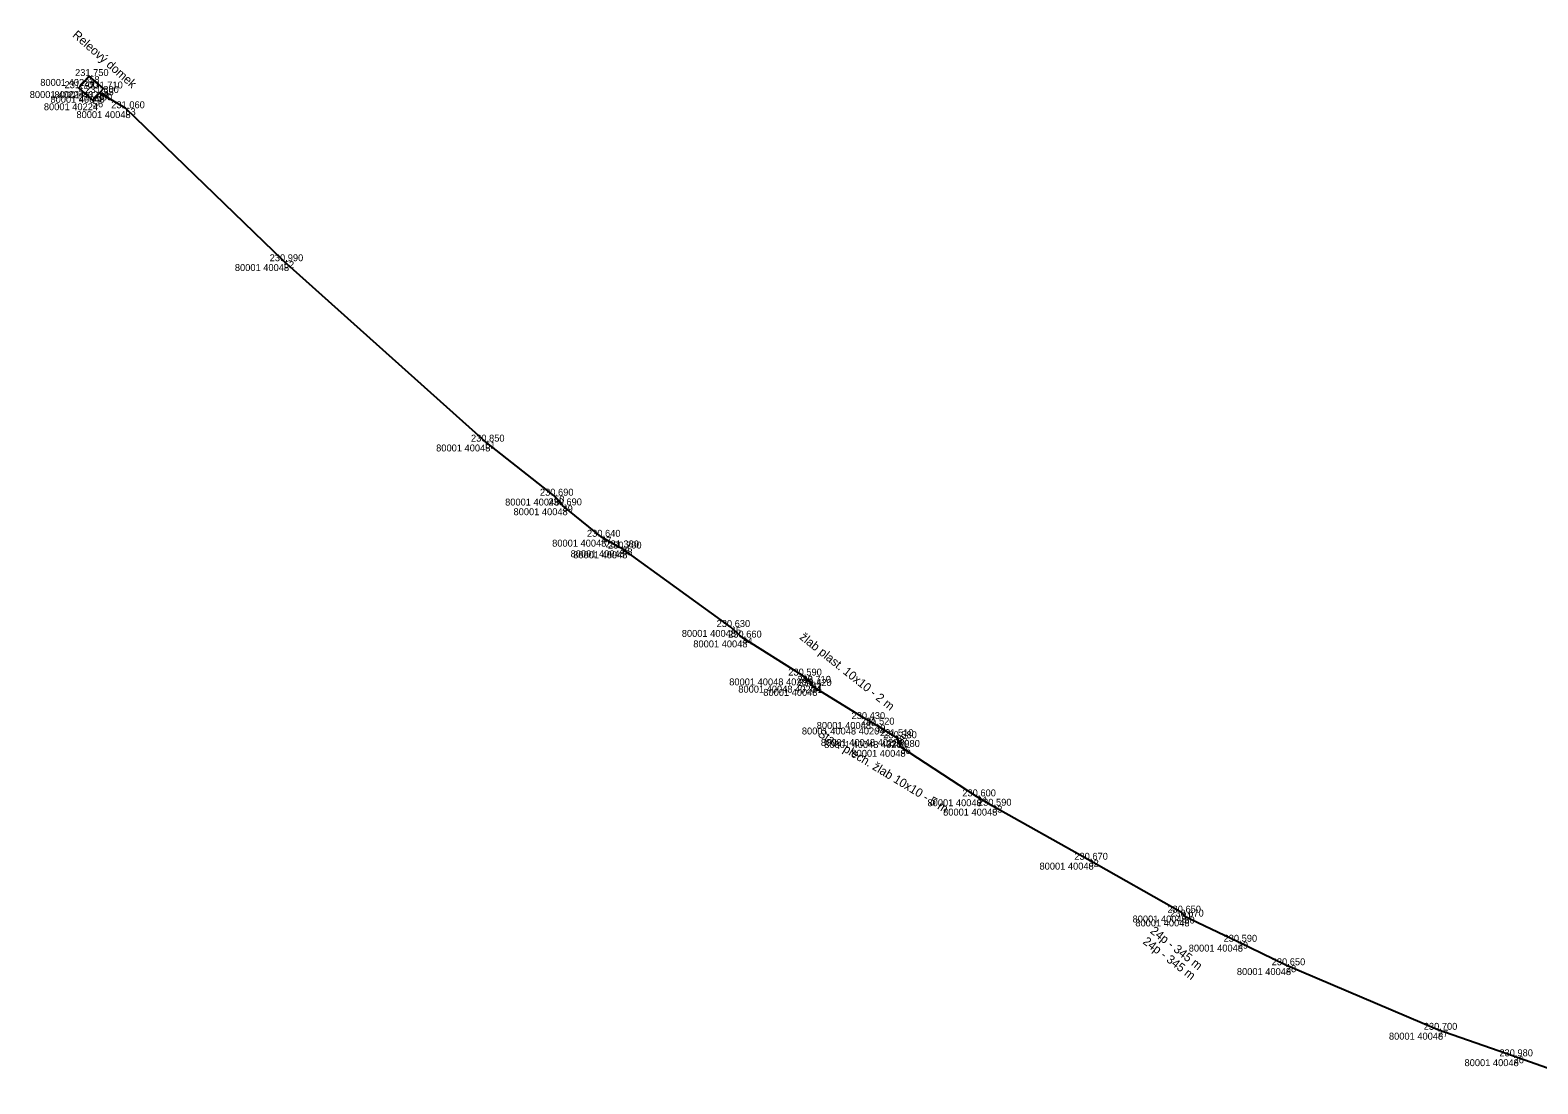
# Model space of a CAD drawing. Extents: x -771675 to -771031, y -1050148 to -1049817.
# Drawn here: x -771674.9 to -771414.2, y -1049999 to -1049816.9 of the extents above; entities that cross this region are included whole.
import ezdxf

# ---------------------------------------------------------------- set-up
doc = ezdxf.new("R2010")
doc.units = 0
for name, color, linetype in [('Vrstva 28', 7, 'Continuous'), ('Vrstva 35', 7, 'Continuous'), ('Vrstva 36', 7, 'Continuous'), ('Vrstva 60', 7, 'Continuous'), ('Vrstva 61', 7, 'Continuous'), ('Vrstva 62', 7, 'Continuous')]:
    doc.layers.add(name, color=color, linetype=linetype)

msp = doc.modelspace()

# ---------------------------------------------------------------- linework, layer by layer
at = {"layer": 'Vrstva 28'}
msp.add_lwpolyline([(-771404.94, -1049999), (-771418.45, -1049994.24), (-771431.52, -1049989.66), (-771457.81, -1049978.5), (-771466.13, -1049974.44), (-771475.36, -1049970.09), (-771475.84, -1049969.41), (-771491.93, -1049960.27), (-771508.59, -1049950.93), (-771511.29, -1049949.31), (-771524.44, -1049940.77), (-771524.96, -1049939.26), (-771525.54, -1049938.9), (-771528.82, -1049936.91), (-771530.44, -1049935.95), (-771539.68, -1049930.24), (-771539.81, -1049929.68), (-771541.38, -1049928.43), (-771551.78, -1049921.86), (-771553.77, -1049920.04), (-771572.54, -1049906.47), (-771572.99, -1049906.28), (-771576.18, -1049904.44), (-771582.86, -1049899.01), (-771584.31, -1049897.34), (-771596.23, -1049887.99), (-771631.03, -1049856.81), (-771658.42, -1049830.37), (-771662.91, -1049827.72)], dxfattribs=at)
msp.add_lwpolyline([(-771404.94, -1049999), (-771418.45, -1049994.24), (-771431.52, -1049989.66), (-771457.81, -1049978.5), (-771466.13, -1049974.44), (-771475.36, -1049970.09), (-771475.84, -1049969.41), (-771491.93, -1049960.27), (-771508.59, -1049950.93), (-771511.29, -1049949.31), (-771524.44, -1049940.77), (-771524.96, -1049939.26), (-771525.54, -1049938.9), (-771528.82, -1049936.91), (-771530.44, -1049935.95), (-771539.68, -1049930.24), (-771539.81, -1049929.68), (-771541.38, -1049928.43), (-771551.78, -1049921.86), (-771553.77, -1049920.04), (-771572.54, -1049906.47), (-771572.99, -1049906.28), (-771576.18, -1049904.44), (-771582.86, -1049899.01), (-771584.31, -1049897.34), (-771596.23, -1049887.99), (-771631.03, -1049856.81), (-771658.42, -1049830.37), (-771662.91, -1049827.72)], dxfattribs=at)
at = {"layer": 'Vrstva 35'}
msp.add_line((-771541.38, -1049928.43), (-771539.81, -1049929.68), dxfattribs=at)
msp.add_lwpolyline([(-771524.96, -1049939.26), (-771525.54, -1049938.9), (-771528.82, -1049936.91)], dxfattribs=at)
at = {"layer": 'Vrstva 36'}
msp.add_lwpolyline([(-771664.68, -1049824.8), (-771666.5, -1049826.9), (-771664.06, -1049829.01), (-771662.23, -1049826.95), (-771664.68, -1049824.8)], dxfattribs=at)
at = {"layer": 'Vrstva 60'}
for p, q in [((-771664.68, -1049824.8), (-771664.68, -1049824.8)), ((-771666.5, -1049826.9), (-771666.5, -1049826.9)), ((-771664.06, -1049829.01), (-771664.06, -1049829.01)), ((-771662.91, -1049827.72), (-771662.91, -1049827.72)), ((-771662.23, -1049826.95), (-771662.23, -1049826.95)), ((-771658.42, -1049830.37), (-771658.42, -1049830.37)), ((-771631.03, -1049856.81), (-771631.03, -1049856.81)), ((-771596.23, -1049887.99), (-771596.23, -1049887.99)), ((-771584.31, -1049897.34), (-771584.31, -1049897.34)), ((-771582.86, -1049899.01), (-771582.86, -1049899.01)), ((-771576.18, -1049904.44), (-771576.18, -1049904.44)), ((-771572.99, -1049906.28), (-771572.99, -1049906.28)), ((-771572.54, -1049906.47), (-771572.54, -1049906.47)), ((-771553.77, -1049920.04), (-771553.77, -1049920.04)), ((-771551.78, -1049921.86), (-771551.78, -1049921.86)), ((-771541.38, -1049928.43), (-771541.38, -1049928.43)), ((-771539.81, -1049929.68), (-771539.81, -1049929.68)), ((-771539.68, -1049930.24), (-771539.68, -1049930.24)), ((-771530.44, -1049935.95), (-771530.44, -1049935.95)), ((-771528.82, -1049936.91), (-771528.82, -1049936.91)), ((-771525.54, -1049938.9), (-771525.54, -1049938.9)), ((-771524.96, -1049939.26), (-771524.96, -1049939.26)), ((-771524.44, -1049940.77), (-771524.44, -1049940.77)), ((-771511.29, -1049949.31), (-771511.29, -1049949.31)), ((-771508.59, -1049950.93), (-771508.59, -1049950.93)), ((-771491.93, -1049960.27), (-771491.93, -1049960.27)), ((-771475.84, -1049969.41), (-771475.84, -1049969.41)), ((-771475.36, -1049970.09), (-771475.36, -1049970.09)), ((-771466.13, -1049974.44), (-771466.13, -1049974.44)), ((-771457.81, -1049978.5), (-771457.81, -1049978.5)), ((-771431.52, -1049989.66), (-771431.52, -1049989.66)), ((-771418.45, -1049994.24), (-771418.45, -1049994.24))]:
    msp.add_line(p, q, dxfattribs=at)

# ---------------------------------------------------------------- texts
at = {"layer": 'Vrstva 28'}
for rotation, p in [(321.8001, (-771481.39, -1049972.81)), (322.6224, (-771482.67, -1049974.64))]:
    msp.add_text('24p - 345 m', height=1.5, rotation=rotation, dxfattribs=at).set_placement(p)
at = {"layer": 'Vrstva 35'}
for s, rotation, p in [('žlab plast. 10x10 - 2 m', 321.474, (-771542, -1049922)), ('Stav. plech. žlab 10x10 - 5 m', 328.7545, (-771538.86, -1049938.83))]:
    msp.add_text(s, height=1.5, rotation=rotation, dxfattribs=at).set_placement(p)
at = {"layer": 'Vrstva 36'}
msp.add_text('Releový domek', height=1.5, rotation=318.7314, dxfattribs=at).set_placement((-771667.69, -1049817.89))
at = {"layer": 'Vrstva 60'}
for s, p in [('58', (-771664.68, -1049826)), ('57', (-771666.5, -1049828.1)), ('56', (-771664.06, -1049830.21)), ('54', (-771662.91, -1049828.92)), ('55', (-771662.23, -1049828.15)), ('53', (-771658.42, -1049831.57)), ('52', (-771631.03, -1049858.01)), ('51', (-771596.23, -1049889.19)), ('50', (-771584.31, -1049898.54)), ('49', (-771582.86, -1049900.21)), ('47', (-771576.18, -1049905.64)), ('46', (-771572.99, -1049907.48)), ('48', (-771572.54, -1049907.67)), ('45', (-771553.77, -1049921.24)), ('44', (-771551.78, -1049923.06)), ('43', (-771541.38, -1049929.63)), ('42', (-771539.81, -1049930.88)), ('41', (-771539.68, -1049931.44)), ('40', (-771530.44, -1049937.15)), ('39', (-771528.82, -1049938.11)), ('38', (-771525.54, -1049940.1)), ('37', (-771524.96, -1049940.46)), ('35', (-771524.44, -1049941.97)), ('34', (-771511.29, -1049950.51)), ('33', (-771508.59, -1049952.13)), ('32', (-771491.93, -1049961.47)), ('31', (-771475.84, -1049970.61)), ('30', (-771475.36, -1049971.29)), ('29', (-771466.13, -1049975.64)), ('28', (-771457.81, -1049979.7)), ('27', (-771431.52, -1049990.86)), ('26', (-771418.45, -1049995.44))]:
    msp.add_text(s, height=1.2, dxfattribs=at).set_placement(p)
at = {"layer": 'Vrstva 61'}
for s, p in [('231.750', (-771667.13, -1049824.8)), ('231.700', (-771668.95, -1049826.9)), ('231.300', (-771665.36, -1049827.72)), ('231.710', (-771664.68, -1049826.95)), ('231.650', (-771666.51, -1049829.01)), ('231.060', (-771660.87, -1049830.37)), ('230.990', (-771633.48, -1049856.81)), ('230.850', (-771598.68, -1049887.99)), ('230.690', (-771586.76, -1049897.34)), ('230.690', (-771585.31, -1049899.01)), ('230.640', (-771578.63, -1049904.44)), ('231.380', (-771575.44, -1049906.28)), ('230.700', (-771574.99, -1049906.47)), ('230.630', (-771556.22, -1049920.04)), ('230.660', (-771554.23, -1049921.86)), ('230.590', (-771543.83, -1049928.43)), ('230.710', (-771542.26, -1049929.68)), ('230.420', (-771542.13, -1049930.24)), ('230.430', (-771532.89, -1049935.95)), ('231.520', (-771531.27, -1049936.91)), ('231.510', (-771527.99, -1049938.9)), ('230.580', (-771527.41, -1049939.26)), ('229.980', (-771526.89, -1049940.77)), ('230.600', (-771513.74, -1049949.31)), ('230.590', (-771511.04, -1049950.93)), ('230.670', (-771494.38, -1049960.27)), ('230.650', (-771478.29, -1049969.41)), ('230.670', (-771477.81, -1049970.09)), ('230.590', (-771468.58, -1049974.44)), ('230.650', (-771460.26, -1049978.5)), ('230.700', (-771433.97, -1049989.66)), ('230.980', (-771420.9, -1049994.24))]:
    msp.add_text(s, height=1.2, dxfattribs=at).set_placement(p)
at = {"layer": 'Vrstva 62'}
for s, p in [('80001 40224', (-771673.14, -1049826.5)), ('80001 40224', (-771674.96, -1049828.6)), ('80001 40048', (-771671.38, -1049829.42)), ('80001 40224', (-771670.69, -1049828.65)), ('80001 40224', (-771672.52, -1049830.71)), ('80001 40048', (-771666.89, -1049832.07)), ('80001 40048', (-771639.5, -1049858.51)), ('80001 40048', (-771604.7, -1049889.69)), ('80001 40048', (-771592.78, -1049899.04)), ('80001 40048', (-771591.33, -1049900.71)), ('80001 40048', (-771584.65, -1049906.14)), ('80001 40048', (-771581.46, -1049907.98)), ('80001 40048', (-771581.01, -1049908.17)), ('80001 40048', (-771562.24, -1049921.74)), ('80001 40048', (-771560.25, -1049923.56)), ('80001 40048 40204', (-771554.04, -1049930.13)), ('80001 40048 40204', (-771552.47, -1049931.38)), ('80001 40048', (-771548.15, -1049931.94)), ('80001 40048 40204', (-771541.48, -1049938.61)), ('80001 40048', (-771538.91, -1049937.65)), ('80001 40048 40204', (-771538.2, -1049940.6)), ('80001 40048 40204', (-771537.62, -1049940.96)), ('80001 40048', (-771532.91, -1049942.47)), ('80001 40048', (-771519.76, -1049951.01)), ('80001 40048', (-771517.06, -1049952.63)), ('80001 40048', (-771500.4, -1049961.97)), ('80001 40048', (-771484.31, -1049971.11)), ('80001 40048', (-771483.83, -1049971.79)), ('80001 40048', (-771474.6, -1049976.14)), ('80001 40048', (-771466.28, -1049980.2)), ('80001 40048', (-771439.99, -1049991.36)), ('80001 40048', (-771426.92, -1049995.94))]:
    msp.add_text(s, height=1.2, dxfattribs=at).set_placement(p)

doc.saveas('drawing.dxf')
